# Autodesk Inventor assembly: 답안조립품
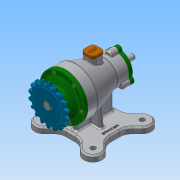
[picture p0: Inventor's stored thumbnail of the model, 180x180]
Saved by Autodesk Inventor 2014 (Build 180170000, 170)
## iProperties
Created: 2018-03
Part Number: 답안조립품
Document SubType Name: Assembly
Designer: user
Author: user
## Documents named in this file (15)
- C:\Users\user\Desktop\480307V1004\답안조립품.iam
- C:\Users\user\Desktop\480307V1004\본체.ipt
- C:\Users\user\Desktop\480307V1004\뒤커버.ipt
- C:\Users\user\Desktop\480307V1004\마개.ipt
- C:\Users\user\Desktop\480307V1004\베어링-6200.ipt
- C:\Users\user\Desktop\480307V1004\베어링-6203.ipt
- C:\Users\user\Desktop\480307V1004\볼트 M4 x 12.ipt
- 볼트 M4 x 12.ipt
- C:\Users\user\Desktop\480307V1004\스프로킷.ipt
- C:\Users\user\Desktop\480307V1004\앞커버.ipt
- C:\Users\user\Desktop\480307V1004\오일 실 10 20 7.ipt
- C:\Users\user\Desktop\480307V1004\오일 실 17 30 8.ipt
- C:\Users\user\Desktop\480307V1004\축.ipt
- C:\Users\user\Desktop\480307V1004\키 5 x 5.ipt
- 키 5 x 5.ipt
